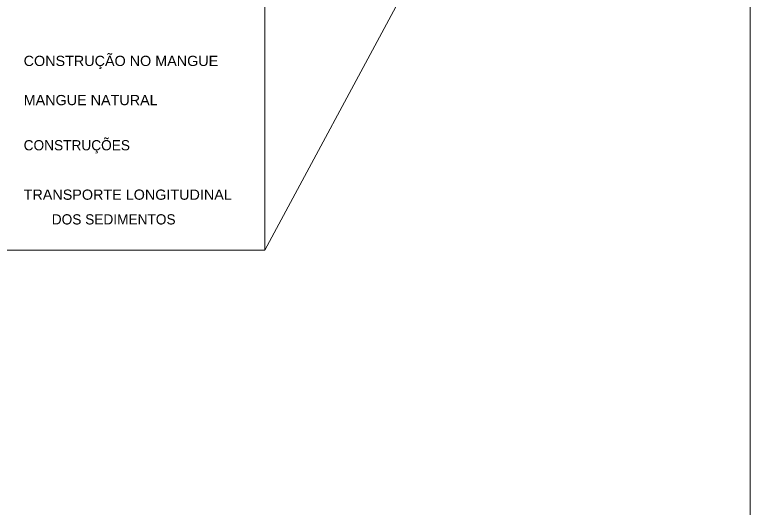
# Model space of a CAD drawing. Extents: x -4.1 to 18.6, y -18.7 to 13.4.
# Drawn here: x 9.93 to 18.56, y -2.41 to 3.37 of the extents above; entities that cross this region are included whole.
import ezdxf

# ---------------------------------------------------------------- set-up
doc = ezdxf.new("R2010")
doc.units = 0
doc.header["$LTSCALE"] = 0.072
doc.layers.add('1', color=7, linetype='Continuous', lineweight=13)

msp = doc.modelspace()

# ---------------------------------------------------------------- linework, layer by layer
at = {"layer": '1'}
msp.add_line((15.55, 5.6), (12.86, 0.61), dxfattribs=at)
msp.add_lwpolyline([(18.56, -18.67), (18.56, 13.4), (-4.12, 13.4), (-4.12, -18.67)], close=True, dxfattribs=at)
msp.add_lwpolyline([(7.07, 0.61), (12.86, 0.61), (12.86, 4.2)], dxfattribs=at)
for points in [[(12.86, 4.2), (12.64, 4.31), (12.44, 4.4), (12.24, 4.48), (12.05, 4.57), (11.83, 4.64), (11.6, 4.69), (11.35, 4.77), (11.15, 4.84), (10.95, 4.85), (10.7, 4.83), (10.55, 4.69), (10.43, 4.51), (10.3, 4.33), (10.16, 4.14), (10.04, 3.96), (9.9, 3.79), (9.75, 3.6), (9.57, 3.41), (9.38, 3.23), (9.2, 3.09), (9.02, 2.95), (8.88, 2.78), (8.73, 2.58), (8.57, 2.41), (8.38, 2.23), (8.21, 2.07), (8.07, 1.9), (7.92, 1.71), (7.77, 1.55), (7.61, 1.39), (7.5, 1.21), (7.35, 1.04), (7.25, 0.85), (7.1, 0.66), (7.07, 0.61)], [(7.07, 0.61), (7.1, 0.66), (7.25, 0.85), (7.35, 1.04), (7.5, 1.21), (7.61, 1.39), (7.77, 1.55), (7.92, 1.71), (8.07, 1.9), (8.21, 2.07), (8.38, 2.23), (8.57, 2.41), (8.73, 2.58), (8.88, 2.78), (9.02, 2.95), (9.2, 3.09), (9.38, 3.23), (9.57, 3.41), (9.75, 3.6), (9.9, 3.79), (10.04, 3.96), (10.16, 4.14), (10.3, 4.33), (10.43, 4.51), (10.55, 4.69), (10.7, 4.83), (10.95, 4.85), (11.15, 4.84), (11.35, 4.77), (11.6, 4.69), (11.83, 4.64), (12.05, 4.57), (12.24, 4.48), (12.44, 4.4), (12.64, 4.31), (12.86, 4.2)]]:
    msp.add_spline(points, degree=3, dxfattribs=at)

# ---------------------------------------------------------------- texts
at = {"layer": '1', "width": 1.05}
for s, p in [('CONSTRUÇÃO NO MANGUE', (10.03, 2.77)), ('MANGUE NATURAL', (10.03, 2.31)), ('TRANSPORTE LONGITUDINAL', (10.03, 1.2))]:
    msp.add_text(s, height=0.12, dxfattribs=at).set_placement(p)
at = {"layer": '1'}
for s, p in [('CONSTRUÇÕES', (10.03, 1.78)), ('DOS SEDIMENTOS', (10.36, 0.91))]:
    msp.add_text(s, height=0.12, dxfattribs=at).set_placement(p)

doc.saveas('drawing.dxf')
